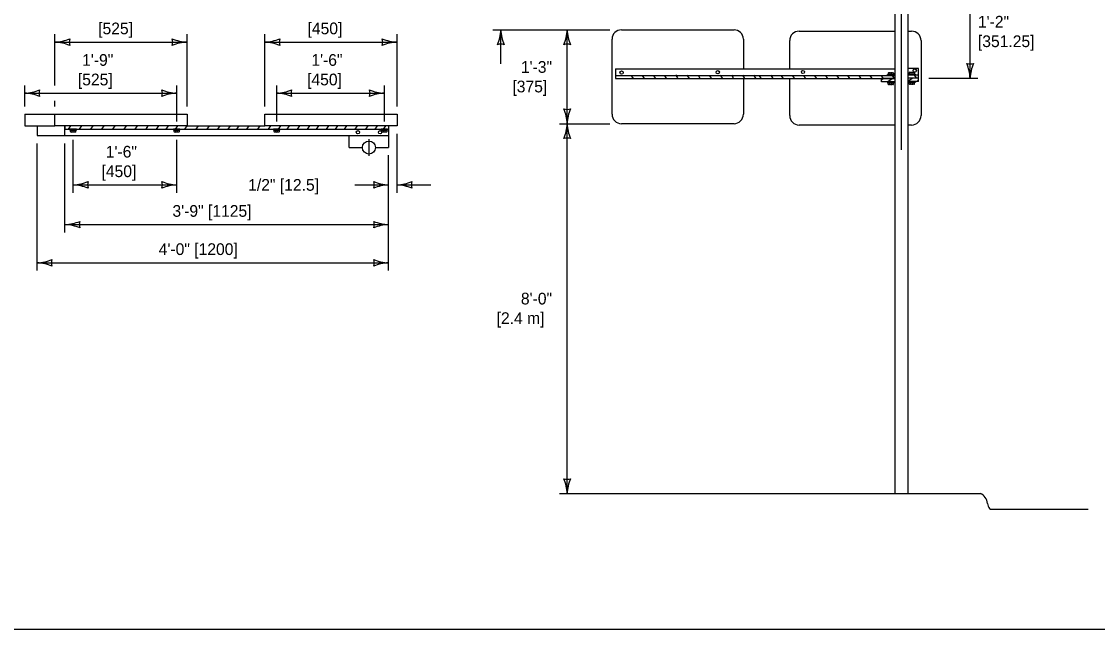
# Model space of a CAD drawing. Extents: x 49991.4 to 50021, y 49987.6 to 50011.4.
# Drawn here: x 50003.25 to 50008.76, y 49987.8 to 49990.91 of the extents above; entities that cross this region are included whole.
import ezdxf

# ---------------------------------------------------------------- set-up
doc = ezdxf.new("R2010")
doc.units = 0
for name, color, linetype in [('Level 1', 7, 'Continuous'), ('Level 2', 7, 'Continuous'), ('Level 3', 7, 'Continuous'), ('Level 4', 7, 'Continuous'), ('Level 5', 7, 'Continuous')]:
    doc.layers.add(name, color=color, linetype=linetype)

msp = doc.modelspace()

# ---------------------------------------------------------------- linework, layer by layer
at = {"layer": 'Level 1'}
for p, q in [((50007.7209, 49993.1079), (50007.721, 49988.4948)), ((50007.7873, 49993.1079), (50007.7873, 49988.4948)), ((50006.3205, 49990.8698), (50006.8973, 49990.8698)), ((50007.2306, 49990.8629), (50007.7209, 49990.8628)), ((50007.7873, 49990.8628), (50007.8074, 49990.8629)), ((50006.2725, 49990.4372), (50006.2725, 49990.8217)), ((50006.9454, 49990.8217), (50006.9454, 49990.6697)), ((50007.1826, 49990.6697), (50007.1826, 49990.8148)), ((50007.8555, 49990.8148), (50007.8555, 49990.4303)), ((50006.2895, 49990.6697), (50006.2895, 49990.6197)), ((50006.2895, 49990.6697), (50007.718, 49990.6697)), ((50007.8419, 49990.6717), (50007.7877, 49990.6717)), ((50007.8419, 49990.605), (50007.8419, 49990.6717)), ((50006.2895, 49990.6365), (50007.7184, 49990.6365)), ((50006.2895, 49990.6197), (50007.6523, 49990.6197)), ((50006.3706, 49990.635), (50006.3815, 49990.6188)), ((50006.4275, 49990.6351), (50006.4376, 49990.6202)), ((50006.4851, 49990.634), (50006.4945, 49990.62)), ((50006.5412, 49990.635), (50006.552, 49990.6192)), ((50006.5983, 49990.6385), (50006.6084, 49990.6236)), ((50006.6559, 49990.6374), (50006.6668, 49990.6212)), ((50006.7128, 49990.6375), (50006.7229, 49990.6226)), ((50006.7704, 49990.6364), (50006.7798, 49990.6224)), ((50006.8265, 49990.6374), (50006.8373, 49990.6215)), ((50006.8838, 49990.637), (50006.8931, 49990.6232)), ((50006.8838, 49990.637), (50006.8931, 49990.6232)), ((50006.8838, 49990.637), (50006.8931, 49990.6232)), ((50006.9406, 49990.6369), (50006.9515, 49990.6207)), ((50006.9454, 49990.6197), (50006.9454, 49990.4372)), ((50006.9975, 49990.637), (50007.0076, 49990.6221)), ((50007.0246, 49990.6359), (50007.034, 49990.6219)), ((50007.0855, 49990.637), (50007.0964, 49990.6208)), ((50007.138, 49990.6366), (50007.1489, 49990.6203)), ((50007.1826, 49990.4303), (50007.1826, 49990.6197)), ((50007.1949, 49990.6366), (50007.205, 49990.6217)), ((50007.2525, 49990.6355), (50007.2619, 49990.6215)), ((50007.3086, 49990.6366), (50007.3194, 49990.6207)), ((50007.3659, 49990.6362), (50007.3752, 49990.6223)), ((50007.3659, 49990.6362), (50007.3752, 49990.6223)), ((50007.3659, 49990.6362), (50007.3752, 49990.6223)), ((50007.4227, 49990.6361), (50007.4337, 49990.6198)), ((50007.4796, 49990.6362), (50007.4897, 49990.6213)), ((50007.5372, 49990.635), (50007.5466, 49990.6211)), ((50007.5934, 49990.6361), (50007.6041, 49990.6202)), ((50007.6506, 49990.6357), (50007.66, 49990.6218)), ((50007.6506, 49990.6357), (50007.66, 49990.6218)), ((50007.6506, 49990.6357), (50007.66, 49990.6218)), ((50007.6523, 49990.6137), (50007.6615, 49990.6198)), ((50007.72, 49990.6197), (50007.6523, 49990.6197)), ((50007.6523, 49990.6197), (50007.7184, 49990.6197)), ((50007.6523, 49990.603), (50007.6523, 49990.6196)), ((50007.7187, 49990.603), (50007.6523, 49990.603)), ((50007.6817, 49990.6029), (50007.7062, 49990.6195)), ((50007.6865, 49990.6477), (50007.6865, 49990.6415)), ((50007.6889, 49990.6502), (50007.7116, 49990.6502)), ((50007.689, 49990.6502), (50007.7116, 49990.6502)), ((50007.6956, 49990.6502), (50007.6956, 49990.6415)), ((50007.7049, 49990.6502), (50007.7049, 49990.6415)), ((50007.7075, 49990.6356), (50007.7171, 49990.6213)), ((50007.7075, 49990.6356), (50007.7171, 49990.6213)), ((50007.7075, 49990.6356), (50007.7171, 49990.6213)), ((50007.7141, 49990.6477), (50007.7141, 49990.6415)), ((50007.8419, 49990.6217), (50007.7869, 49990.6217)), ((50007.8419, 49990.6217), (50007.7869, 49990.6217)), ((50007.7871, 49990.6062), (50007.8096, 49990.6215)), ((50007.8419, 49990.6384), (50007.7873, 49990.6384)), ((50007.8419, 49990.6217), (50007.7873, 49990.6217)), ((50007.8419, 49990.605), (50007.7877, 49990.605)), ((50007.8419, 49990.6217), (50007.7882, 49990.6217)), ((50007.7948, 49990.6497), (50007.7948, 49990.6435)), ((50007.7974, 49990.6523), (50007.8201, 49990.6523)), ((50007.8039, 49990.6522), (50007.8039, 49990.6435)), ((50007.8132, 49990.6522), (50007.8132, 49990.6435)), ((50007.8208, 49990.6383), (50007.8319, 49990.6217)), ((50007.8208, 49990.6383), (50007.8309, 49990.6232)), ((50007.8208, 49990.6383), (50007.8309, 49990.6232)), ((50007.8224, 49990.6497), (50007.8224, 49990.6435)), ((50007.8311, 49990.6054), (50007.8419, 49990.6126)), ((50007.6873, 49990.5918), (50007.6873, 49990.598)), ((50007.7124, 49990.5892), (50007.6898, 49990.5892)), ((50007.7125, 49990.5892), (50007.6898, 49990.5892)), ((50007.6965, 49990.5892), (50007.6965, 49990.598)), ((50007.7058, 49990.5892), (50007.7058, 49990.598)), ((50007.715, 49990.5918), (50007.715, 49990.598)), ((50007.7946, 49990.5937), (50007.7946, 49990.5999)), ((50007.8197, 49990.5911), (50007.797, 49990.5911)), ((50007.8197, 49990.5911), (50007.797, 49990.5911)), ((50007.8038, 49990.5911), (50007.8038, 49990.5999)), ((50007.8131, 49990.5911), (50007.8131, 49990.5999)), ((50007.8222, 49990.5937), (50007.8222, 49990.5999)), ((50006.8973, 49990.3891), (50006.3205, 49990.3891)), ((50007.7209, 49990.3822), (50007.2306, 49990.3822)), ((50007.8074, 49990.3822), (50007.7873, 49990.3822)), ((50003.4694, 49990.3769), (50003.4694, 49990.3602)), ((50003.4694, 49990.3284), (50003.4694, 49990.3769)), ((50003.4694, 49990.3602), (50005.1273, 49990.3602)), ((50003.4694, 49990.3284), (50004.9247, 49990.3284)), ((50003.4878, 49990.3602), (50003.4996, 49990.3776)), ((50003.4977, 49990.3492), (50003.4977, 49990.3555)), ((50003.5003, 49990.3466), (50003.5229, 49990.3466)), ((50003.5069, 49990.3491), (50003.5069, 49990.3555)), ((50003.5161, 49990.3491), (50003.5161, 49990.3555)), ((50003.5254, 49990.3492), (50003.5254, 49990.3555)), ((50003.5446, 49990.3602), (50003.5564, 49990.3776)), ((50003.6015, 49990.3602), (50003.6133, 49990.3776)), ((50003.6583, 49990.3602), (50003.6701, 49990.3776)), ((50003.7152, 49990.3602), (50003.727, 49990.3776)), ((50003.7721, 49990.3602), (50003.7839, 49990.3776)), ((50003.8289, 49990.3602), (50003.8407, 49990.3776)), ((50003.8846, 49990.3602), (50003.8964, 49990.3776)), ((50003.9383, 49990.3602), (50003.9501, 49990.3776)), ((50003.9878, 49990.3602), (50003.9997, 49990.3776)), ((50004.0281, 49990.3492), (50004.0281, 49990.3555)), ((50004.0307, 49990.3466), (50004.0533, 49990.3466)), ((50004.035, 49990.3602), (50004.0471, 49990.3776)), ((50004.0373, 49990.3491), (50004.0373, 49990.3555)), ((50004.0465, 49990.3491), (50004.0465, 49990.3555)), ((50004.0558, 49990.3492), (50004.0558, 49990.3555)), ((50004.084, 49990.3602), (50004.096, 49990.3778)), ((50004.096, 49990.3778), (50004.4937, 49990.3778)), ((50004.141, 49990.3602), (50004.1529, 49990.3778)), ((50004.1978, 49990.3602), (50004.2097, 49990.3778)), ((50004.2527, 49990.3602), (50004.2646, 49990.3778)), ((50004.3054, 49990.3602), (50004.3174, 49990.3778)), ((50004.3502, 49990.3602), (50004.3621, 49990.3778)), ((50004.4007, 49990.3602), (50004.4126, 49990.3778)), ((50004.4575, 49990.3602), (50004.4694, 49990.3778)), ((50004.5124, 49990.3602), (50004.5245, 49990.378)), ((50004.5406, 49990.3492), (50004.5406, 49990.3555)), ((50004.5432, 49990.3466), (50004.5658, 49990.3466)), ((50004.5498, 49990.3491), (50004.5498, 49990.3555)), ((50004.559, 49990.3491), (50004.559, 49990.3555)), ((50004.5636, 49990.3602), (50004.5754, 49990.3777)), ((50004.5683, 49990.3492), (50004.5683, 49990.3555)), ((50004.6075, 49990.3602), (50004.6193, 49990.3778)), ((50004.6605, 49990.3602), (50004.6723, 49990.3778)), ((50004.7118, 49990.3602), (50004.7237, 49990.3778)), ((50004.7587, 49990.3602), (50004.7707, 49990.3778)), ((50004.8091, 49990.3602), (50004.8209, 49990.3778)), ((50004.8562, 49990.3602), (50004.868, 49990.3778)), ((50004.902, 49990.3602), (50004.9138, 49990.3778)), ((50004.9247, 49990.2671), (50004.9247, 49990.3284)), ((50004.9247, 49990.3284), (50005.0587, 49990.3284)), ((50004.9563, 49990.3602), (50004.9678, 49990.3778)), ((50005.0109, 49990.3602), (50005.0228, 49990.3778)), ((50005.0587, 49990.3284), (50005.1273, 49990.3284)), ((50005.059, 49990.3602), (50005.0708, 49990.3778)), ((50005.092, 49990.3492), (50005.092, 49990.3555)), ((50005.0946, 49990.3466), (50005.1172, 49990.3466)), ((50005.1012, 49990.3491), (50005.1012, 49990.3555)), ((50005.102, 49990.3602), (50005.1139, 49990.3778)), ((50005.1104, 49990.3491), (50005.1104, 49990.3555)), ((50005.1197, 49990.3492), (50005.1197, 49990.3555)), ((50005.1273, 49990.3778), (50005.1273, 49990.2671)), ((50004.9247, 49990.2671), (50004.9936, 49990.2671)), ((50005.0601, 49990.2671), (50005.1273, 49990.2671)), ((50006.0024, 49988.4948), (50008.1594, 49988.4948)), ((50008.2115, 49988.4155), (50008.7111, 49988.4155))]:
    msp.add_line(p, q, dxfattribs=at)
for points in [[(49999.3835, 49998.9992), (50016.7501, 49998.9992), (50016.7501, 49987.7988), (49999.3835, 49987.7988)], [(50007.6837, 49990.6366), (50007.6837, 49990.6413), (50007.7166, 49990.6413), (50007.7166, 49990.6366)], [(50007.7177, 49990.6028), (50007.7177, 49990.5982), (50007.6848, 49990.5982), (50007.6848, 49990.6028)], [(50007.792, 49990.6386), (50007.792, 49990.6433), (50007.8249, 49990.6433), (50007.8249, 49990.6386)], [(50007.825, 49990.6047), (50007.825, 49990.6001), (50007.7921, 49990.6001), (50007.7921, 49990.6047)], [(50004.0948, 49990.4371), (50004.0948, 49990.3776), (50003.4179, 49990.3776), (50003.4179, 49990.4371)], [(50005.1707, 49990.4374), (50005.1707, 49990.3778), (50004.4937, 49990.3778), (50004.4937, 49990.4374)], [(50003.495, 49990.3602), (50003.495, 49990.3555), (50003.5278, 49990.3555), (50003.5278, 49990.3602)], [(50004.0254, 49990.3602), (50004.0254, 49990.3555), (50004.0582, 49990.3555), (50004.0582, 49990.3602)], [(50004.5379, 49990.3602), (50004.5379, 49990.3555), (50004.5707, 49990.3555), (50004.5707, 49990.3602)], [(50005.0893, 49990.3602), (50005.0893, 49990.3555), (50005.1221, 49990.3555), (50005.1221, 49990.3602)]]:
    msp.add_lwpolyline(points, close=True, dxfattribs=at)
for centre, radius in [((50006.3211, 49990.6509), 0.00843), ((50006.8138, 49990.6529), 0.00843), ((50007.2507, 49990.6539), 0.00843), ((50007.8235, 49990.6612), 0.00843), ((50004.9699, 49990.3455), 0.00843), ((50005.0837, 49990.3455), 0.00843), ((50005.0269, 49990.2671), 0.0333)]:
    msp.add_circle(centre, radius, dxfattribs=at)
for centre, radius, start, end in [((50006.3205, 49990.8217), 0.0481, 90, 180), ((50006.8973, 49990.8217), 0.0481, 0, 90), ((50007.2306, 49990.8148), 0.0481, 90, 180), ((50007.8074, 49990.8148), 0.0481, 0, 90), ((50007.6891, 49990.6477), 0.00257, 90, 180), ((50007.6931, 49990.6477), 0.00257, 0, 90), ((50007.6983, 49990.6477), 0.00257, 90, 180), ((50007.7023, 49990.6477), 0.00257, 0, 90), ((50007.7075, 49990.6477), 0.00257, 90, 180), ((50007.7115, 49990.6477), 0.00257, 0, 90), ((50007.7974, 49990.6497), 0.00257, 90, 180), ((50007.8013, 49990.6497), 0.00257, 0, 90), ((50007.8065, 49990.6497), 0.00257, 90, 180), ((50007.8106, 49990.6497), 0.00257, 0, 90), ((50007.8158, 49990.6497), 0.00257, 90, 180), ((50007.8198, 49990.6497), 0.00257, 0, 90), ((50007.6899, 49990.5918), 0.00257, 180, 270), ((50007.694, 49990.5918), 0.00257, 270, 0), ((50007.6991, 49990.5918), 0.00257, 180, 270), ((50007.7032, 49990.5918), 0.00257, 270, 0), ((50007.7083, 49990.5918), 0.00257, 180, 270), ((50007.7124, 49990.5918), 0.00257, 270, 0), ((50007.7971, 49990.5937), 0.00257, 180, 270), ((50007.8012, 49990.5937), 0.00257, 270, 0), ((50007.8064, 49990.5937), 0.00257, 180, 270), ((50007.8104, 49990.5937), 0.00257, 270, 0), ((50007.8156, 49990.5937), 0.00257, 180, 270), ((50007.8196, 49990.5937), 0.00257, 270, 0), ((50006.3205, 49990.4372), 0.0481, 180, 270), ((50006.8973, 49990.4372), 0.0481, 270, 0), ((50007.2306, 49990.4303), 0.0481, 180, 270), ((50007.8074, 49990.4303), 0.0481, 270, 0), ((50003.5003, 49990.3491), 0.00257, 180, 270), ((50003.5044, 49990.3491), 0.00257, 270, 0), ((50003.5095, 49990.3491), 0.00257, 180, 270), ((50003.5136, 49990.3491), 0.00257, 270, 0), ((50003.5187, 49990.3491), 0.00257, 180, 270), ((50003.5228, 49990.3491), 0.00257, 270, 0), ((50004.0307, 49990.3491), 0.00257, 180, 270), ((50004.0348, 49990.3491), 0.00257, 270, 0), ((50004.0399, 49990.3491), 0.00257, 180, 270), ((50004.044, 49990.3491), 0.00257, 270, 0), ((50004.0491, 49990.3491), 0.00257, 180, 270), ((50004.0532, 49990.3491), 0.00257, 270, 0), ((50004.5432, 49990.3491), 0.00257, 180, 270), ((50004.5473, 49990.3491), 0.00257, 270, 0), ((50004.5524, 49990.3491), 0.00257, 180, 270), ((50004.5565, 49990.3491), 0.00257, 270, 0), ((50004.5616, 49990.3491), 0.00257, 180, 270), ((50004.5657, 49990.3491), 0.00257, 270, 0), ((50005.0946, 49990.3491), 0.00257, 180, 270), ((50005.0987, 49990.3491), 0.00257, 270, 0), ((50005.1038, 49990.3491), 0.00257, 180, 270), ((50005.1079, 49990.3491), 0.00257, 270, 0), ((50005.113, 49990.3491), 0.00257, 180, 270), ((50005.1171, 49990.3491), 0.00257, 270, 0), ((50008.1358, 49988.4386), 0.061, 5.6244, 67.2103), ((50008.257, 49988.4512), 0.061, 186.2396, 213.3658)]:
    msp.add_arc(centre, radius, start, end, dxfattribs=at)
msp.add_spline([(50008.2061, 49988.4177), (50008.2074, 49988.4169), (50008.2091, 49988.416), (50008.2115, 49988.4155)], degree=3, dxfattribs=at)
at = {"layer": 'Level 3'}
for p, q in [((50008.107, 49990.6217), (50008.107, 49991.1007)), ((50003.4179, 49990.5854), (50003.4179, 49990.847)), ((50004.0948, 49990.4771), (50004.0948, 49990.847)), ((50004.4937, 49990.4774), (50004.4937, 49990.847)), ((50005.1707, 49990.4774), (50005.1707, 49990.847)), ((50005.6624, 49990.8698), (50006.2605, 49990.8698)), ((50005.7024, 49990.6964), (50005.7024, 49990.8698)), ((50006.0424, 49990.3892), (50006.0424, 49990.8698)), ((50003.4184, 49990.807), (50004.0948, 49990.807)), ((50004.4937, 49990.807), (50005.1707, 49990.807)), ((50007.8955, 49990.6217), (50008.147, 49990.6217)), ((50003.2633, 49990.4771), (50003.2633, 49990.5854)), ((50004.0418, 49990.4002), (50004.0418, 49990.5854)), ((50004.5543, 49990.4002), (50004.5543, 49990.5854)), ((50005.1057, 49990.4002), (50005.1057, 49990.5854)), ((50003.2633, 49990.5454), (50004.0418, 49990.5454)), ((50003.4179, 49990.4771), (50003.4179, 49990.5054)), ((50004.5543, 49990.5454), (50005.1057, 49990.5454)), ((50006.0024, 49990.3892), (50006.2605, 49990.3892)), ((50006.0424, 49988.4948), (50006.0424, 49990.3892)), ((50005.1707, 49990.0356), (50005.1707, 49990.3378)), ((50003.3267, 49989.6365), (50003.3267, 49990.2884)), ((50003.4694, 49989.8322), (50003.4694, 49990.2884)), ((50003.5116, 49990.0356), (50003.5116, 49990.3066)), ((50004.042, 49990.0356), (50004.042, 49990.3066)), ((50005.1273, 49989.6365), (50005.1273, 49990.2271)), ((50003.5116, 49990.0756), (50004.042, 49990.0756)), ((50004.9539, 49990.0756), (50005.1273, 49990.0756)), ((50005.1707, 49990.0756), (50005.3441, 49990.0756)), ((50003.4694, 49989.8722), (50005.1273, 49989.8722)), ((50003.3267, 49989.6765), (50005.1273, 49989.6765))]:
    msp.add_line(p, q, dxfattribs=at)
for centre, radius, start, end in [((50003.4064, 49991.0397), 0.233, 272.8273, 292.0772), ((50003.5461, 49990.807), 0.0548, 162.1388, 197.8612), ((50004.104, 49991.0291), 0.2223, 247.456, 267.6395), ((50003.9666, 49990.807), 0.0548, 342.1388, 17.8612), ((50004.4822, 49991.0397), 0.233, 272.8273, 292.0772), ((50004.6219, 49990.807), 0.0548, 162.1388, 197.8612), ((50005.1799, 49991.0291), 0.2223, 247.456, 267.6395), ((50005.0425, 49990.807), 0.0548, 342.1388, 17.8612), ((50005.4803, 49990.879), 0.2223, 337.456, 357.6395), ((50005.9351, 49990.8813), 0.233, 182.8273, 202.0772), ((50005.8203, 49990.879), 0.2223, 337.456, 357.6395), ((50006.2751, 49990.8813), 0.233, 182.8273, 202.0772), ((50003.4087, 49990.5849), 0.2223, 67.456, 87.6395), ((50004.1063, 49990.5743), 0.233, 92.8273, 112.0772), ((50004.4845, 49990.5849), 0.2223, 67.456, 87.6395), ((50005.1822, 49990.5743), 0.233, 92.8273, 112.0772), ((50005.7024, 49990.7416), 0.0548, 72.1388, 107.8612), ((50006.0424, 49990.7416), 0.0548, 72.1388, 107.8612), ((50008.107, 49990.7499), 0.0548, 252.1388, 287.8612), ((50007.8743, 49990.6102), 0.233, 2.8273, 22.0772), ((50008.3291, 49990.6125), 0.2223, 157.456, 177.6395), ((50003.2518, 49990.7781), 0.233, 272.8273, 292.0772), ((50003.3915, 49990.5454), 0.0548, 162.1388, 197.8612), ((50004.051, 49990.7675), 0.2223, 247.456, 267.6395), ((50003.9136, 49990.5454), 0.0548, 342.1388, 17.8612), ((50004.5428, 49990.7781), 0.233, 272.8273, 292.0772), ((50004.6825, 49990.5454), 0.0548, 162.1388, 197.8612), ((50005.1149, 49990.7675), 0.2223, 247.456, 267.6395), ((50004.9775, 49990.5454), 0.0548, 342.1388, 17.8612), ((50003.2541, 49990.3233), 0.2223, 67.456, 87.6395), ((50004.0533, 49990.3127), 0.233, 92.8273, 112.0772), ((50004.5451, 49990.3233), 0.2223, 67.456, 87.6395), ((50005.1172, 49990.3127), 0.233, 92.8273, 112.0772), ((50006.0424, 49990.5174), 0.0548, 252.1388, 287.8612), ((50005.8097, 49990.3777), 0.233, 2.8273, 22.0772), ((50006.2645, 49990.38), 0.2223, 157.456, 177.6395), ((50005.8203, 49990.3984), 0.2223, 337.456, 357.6395), ((50006.2751, 49990.4007), 0.233, 182.8273, 202.0772), ((50006.0424, 49990.261), 0.0548, 72.1388, 107.8612), ((50003.5001, 49990.3083), 0.233, 272.8273, 292.0772), ((50003.5024, 49989.8535), 0.2223, 67.456, 87.6395), ((50003.6398, 49990.0756), 0.0548, 162.1388, 197.8612), ((50004.0512, 49990.2977), 0.2223, 247.456, 267.6395), ((50003.9138, 49990.0756), 0.0548, 342.1388, 17.8612), ((50004.0535, 49989.8429), 0.233, 92.8273, 112.0772), ((50005.1365, 49990.2977), 0.2223, 247.456, 267.6395), ((50004.9991, 49990.0756), 0.0548, 342.1388, 17.8612), ((50005.1388, 49989.8429), 0.233, 92.8273, 112.0772), ((50005.1592, 49990.3083), 0.233, 272.8273, 292.0772), ((50005.1615, 49989.8535), 0.2223, 67.456, 87.6395), ((50005.2989, 49990.0756), 0.0548, 162.1388, 197.8612), ((50003.4579, 49990.1049), 0.233, 272.8273, 292.0772), ((50003.5976, 49989.8722), 0.0548, 162.1388, 197.8612), ((50005.1365, 49990.0943), 0.2223, 247.456, 267.6395), ((50004.9991, 49989.8722), 0.0548, 342.1388, 17.8612), ((50003.4602, 49989.6501), 0.2223, 67.456, 87.6395), ((50005.1388, 49989.6395), 0.233, 92.8273, 112.0772), ((50003.3152, 49989.9092), 0.233, 272.8273, 292.0772), ((50003.3175, 49989.4544), 0.2223, 67.456, 87.6395), ((50003.4549, 49989.6765), 0.0548, 162.1388, 197.8612), ((50005.1365, 49989.8986), 0.2223, 247.456, 267.6395), ((50004.9991, 49989.6765), 0.0548, 342.1388, 17.8612), ((50005.1388, 49989.4438), 0.233, 92.8273, 112.0772), ((50006.0424, 49988.623), 0.0548, 252.1388, 287.8612), ((50005.8097, 49988.4833), 0.233, 2.8273, 22.0772), ((50006.2645, 49988.4856), 0.2223, 157.456, 177.6395)]:
    msp.add_arc(centre, radius, start, end, dxfattribs=at)
at = {"layer": 'Level 4'}
for p, q in [((50007.7541, 49993.1079), (50007.7541, 49990.2553)), ((50003.2633, 49990.4371), (50003.4179, 49990.4371)), ((50003.2633, 49990.4371), (50003.2633, 49990.3776)), ((50003.2633, 49990.3776), (50003.4179, 49990.3776)), ((50003.3267, 49990.3776), (50003.3267, 49990.3284)), ((50003.3267, 49990.3284), (50003.4694, 49990.3284))]:
    msp.add_line(p, q, dxfattribs=at)
at = {"layer": 'Level 5'}
msp.add_line((50005.0268, 49990.3103), (50005.0268, 49990.2238), dxfattribs=at)

# ---------------------------------------------------------------- texts
at = {"layer": 'Level 2'}
for s, p in [('1\'-2"', (50008.147, 49990.8813)), ('[525]', (50003.6394, 49990.847)), ('[450]', (50004.7121, 49990.847)), ('[351.25]', (50008.147, 49990.7813)), ('1\'-9"', (50003.5572, 49990.6854)), ('1\'-6"', (50004.7317, 49990.6854)), ('1\'-3"', (50005.8054, 49990.6495)), ('[525]', (50003.5354, 49990.5854)), ('[450]', (50004.7099, 49990.5854)), ('[375]', (50005.7619, 49990.5495)), ('1\'-6"', (50003.6783, 49990.2156)), ('[450]', (50003.6565, 49990.1156)), (' 1/2" [12.5]', (50004.3857, 49990.0456)), ('3\'-9" [1125]', (50004.0201, 49989.9122)), ('4\'-0" [1200]', (50003.9497, 49989.7165)), ('8\'-0"', (50005.8054, 49989.4632)), ('[2.4 m]', (50005.681, 49989.3632))]:
    msp.add_text(s, height=0.06, dxfattribs=at).set_placement(p)

doc.saveas('drawing.dxf')
